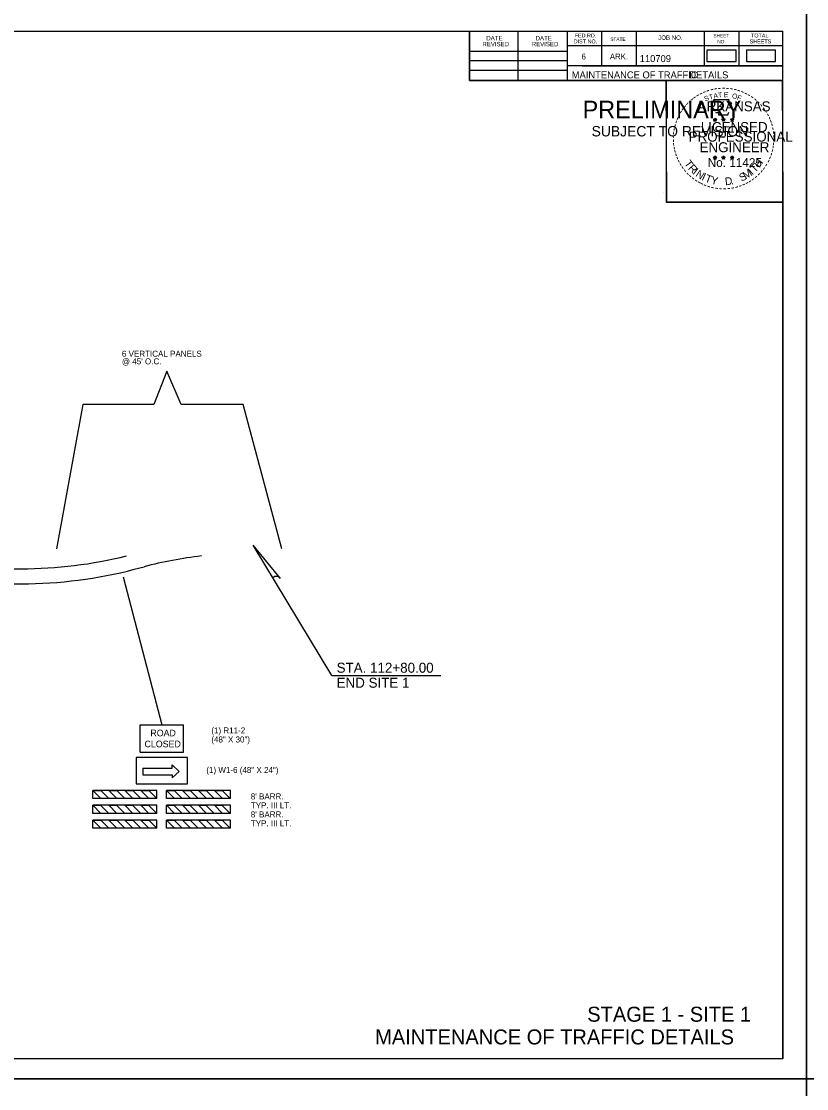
# Model space of a CAD drawing. Extents: x 2829243 to 2838161, y 467639 to 474695.
# Drawn here: x 2830368 to 2831153, y 471502 to 472569 of the extents above; entities that cross this region are included whole.
import ezdxf

# ---------------------------------------------------------------- set-up
doc = ezdxf.new("R2010")
doc.units = 0
for name, color, linetype in [('Default', 7, 'Continuous'), ('R_Border', 7, 'Continuous'), ('R_Border PE', 7, 'Continuous'), ('R_Border Prem', 7, 'Continuous'), ('R_Dimension', 7, 'Continuous'), ('R_MOT', 7, 'Continuous'), ('R_No Plot', 7, 'Continuous')]:
    doc.layers.add(name, color=color, linetype=linetype)

msp = doc.modelspace()

# ---------------------------------------------------------------- linework, layer by layer
at = {"layer": 'Default'}
for points in [[(2831053.2, 472528.5), (2831082.4, 472528.5), (2831082.4, 472540), (2831053.2, 472540)], [(2831092.6, 472528.5), (2831121.7, 472528.5), (2831121.7, 472540), (2831092.6, 472540)]]:
    msp.add_lwpolyline(points, close=True, dxfattribs=at)
at = {"layer": 'R_Border'}
for p, q in [((2829548.2, 472559), (2831129.1, 472559)), ((2830815.9, 472509.6), (2830815.9, 472559)), ((2830864.3, 472509.6), (2830864.3, 472559)), ((2830913.6, 472559), (2830913.6, 472509.6)), ((2830947.8, 472559), (2830947.8, 472524.3)), ((2830982.5, 472559), (2830982.5, 472524.3)), ((2831050.4, 472559), (2831050.4, 472524.3)), ((2831085.1, 472559), (2831085.1, 472524.3)), ((2831129.1, 471531.7), (2831129.1, 472559)), ((2831129.1, 472544.3), (2830913.6, 472544.3)), ((2831129.1, 472544.4), (2831129.1, 472544.4)), ((2830815.9, 472538.9), (2830913.6, 472538.9)), ((2830815.9, 472529.6), (2830913.6, 472529.6)), ((2831129.1, 472524.3), (2830913.6, 472524.3)), ((2830928.4, 472524.3), (2831129.1, 472524.3)), ((2830815.9, 472519.9), (2830913.6, 472519.9)), ((2831129.1, 472509.6), (2830815.9, 472509.6)), ((2831129.1, 471531.7), (2829548.2, 471531.7))]:
    msp.add_line(p, q, dxfattribs=at)
at = {"layer": 'R_Border PE'}
for p, q in [((2831059.6, 472470.8), (2831061.3, 472470.3)), ((2831059.6, 472470.8), (2831060.8, 472470.6)), ((2831059.6, 472470.8), (2831060.8, 472470.2)), ((2831060.2, 472468.8), (2831061.3, 472470.3)), ((2831060.2, 472468.8), (2831060.9, 472470)), ((2831060.2, 472468.8), (2831061.3, 472469.9)), ((2831061.3, 472472.1), (2831061.1, 472470.9)), ((2831061.3, 472470.3), (2831061.3, 472472.1)), ((2831061.3, 472472.1), (2831061.6, 472470.9)), ((2831063, 472470.8), (2831061.3, 472470.3)), ((2831062.4, 472468.8), (2831061.3, 472470.3)), ((2831062.4, 472468.8), (2831061.3, 472469.9)), ((2831063, 472470.8), (2831061.6, 472470.6)), ((2831062.4, 472468.8), (2831061.7, 472470.3)), ((2831063, 472470.8), (2831062, 472470.3)), ((2831067.9, 472470.8), (2831069.7, 472470.3)), ((2831067.9, 472470.8), (2831069.2, 472470.6)), ((2831067.9, 472470.8), (2831069.1, 472470.2)), ((2831068.6, 472468.8), (2831069.7, 472470.3)), ((2831068.6, 472468.8), (2831069.2, 472470)), ((2831068.6, 472468.8), (2831069.7, 472469.9)), ((2831069.7, 472472.1), (2831069.5, 472470.9)), ((2831069.7, 472470.3), (2831069.7, 472472.1)), ((2831069.7, 472472.1), (2831069.9, 472470.9)), ((2831071.4, 472470.8), (2831069.7, 472470.3)), ((2831070.7, 472468.8), (2831069.7, 472470.3)), ((2831070.7, 472468.8), (2831069.7, 472469.9)), ((2831071.4, 472470.8), (2831070, 472470.6)), ((2831070.7, 472468.8), (2831070, 472470.3)), ((2831071.4, 472470.8), (2831070.4, 472470.3)), ((2831076.7, 472470.8), (2831078.5, 472470.2)), ((2831076.7, 472470.8), (2831078, 472470.6)), ((2831076.7, 472470.8), (2831077.9, 472470.2)), ((2831077.4, 472468.7), (2831078.5, 472470.2)), ((2831077.4, 472468.7), (2831078, 472470)), ((2831077.4, 472468.7), (2831078.5, 472469.8)), ((2831078.5, 472472.1), (2831078.3, 472470.8)), ((2831078.5, 472470.2), (2831078.5, 472472.1)), ((2831078.5, 472472.1), (2831078.7, 472470.8)), ((2831080.2, 472470.8), (2831078.5, 472470.2)), ((2831079.5, 472468.7), (2831078.5, 472470.2)), ((2831079.5, 472468.7), (2831078.5, 472469.8)), ((2831080.2, 472470.8), (2831078.8, 472470.5)), ((2831079.5, 472468.7), (2831078.9, 472470.2)), ((2831080.2, 472470.8), (2831079.2, 472470.3)), ((2831059.5, 472433), (2831061.3, 472432.4)), ((2831059.5, 472433), (2831060.8, 472432.8)), ((2831059.5, 472433), (2831060.7, 472432.4)), ((2831060.2, 472430.9), (2831061.3, 472432.4)), ((2831060.2, 472430.9), (2831060.8, 472432.2)), ((2831060.2, 472430.9), (2831061.3, 472432)), ((2831061.3, 472434.3), (2831061.1, 472433)), ((2831061.3, 472432.4), (2831061.3, 472434.3)), ((2831061.3, 472434.3), (2831061.5, 472433)), ((2831063, 472433), (2831061.3, 472432.4)), ((2831062.4, 472430.9), (2831061.3, 472432.4)), ((2831062.4, 472430.9), (2831061.3, 472432)), ((2831063, 472433), (2831061.6, 472432.7)), ((2831062.4, 472430.9), (2831061.7, 472432.4)), ((2831063, 472433), (2831062, 472432.5)), ((2831067.9, 472433), (2831069.6, 472432.4)), ((2831067.9, 472433), (2831069.2, 472432.8)), ((2831067.9, 472433), (2831069.1, 472432.4)), ((2831068.6, 472430.9), (2831069.6, 472432.4)), ((2831068.6, 472430.9), (2831069.2, 472432.2)), ((2831068.6, 472430.9), (2831069.6, 472432)), ((2831069.6, 472434.3), (2831069.4, 472433)), ((2831069.6, 472432.4), (2831069.6, 472434.3)), ((2831069.6, 472434.3), (2831069.9, 472433)), ((2831071.4, 472433), (2831069.6, 472432.4)), ((2831070.7, 472430.9), (2831069.6, 472432.4)), ((2831070.7, 472430.9), (2831069.6, 472432)), ((2831071.4, 472433), (2831069.9, 472432.7)), ((2831070.7, 472430.9), (2831070, 472432.4)), ((2831071.4, 472433), (2831070.4, 472432.5)), ((2831076.7, 472432.9), (2831078.5, 472432.4)), ((2831076.7, 472432.9), (2831078, 472432.7)), ((2831076.7, 472432.9), (2831077.9, 472432.3)), ((2831077.4, 472430.9), (2831078.5, 472432.4)), ((2831077.4, 472430.9), (2831078, 472432.1)), ((2831077.4, 472430.9), (2831078.5, 472432)), ((2831078.5, 472434.2), (2831078.3, 472432.9)), ((2831078.5, 472432.4), (2831078.5, 472434.2)), ((2831078.5, 472434.2), (2831078.7, 472433)), ((2831080.2, 472432.9), (2831078.5, 472432.4)), ((2831079.5, 472430.9), (2831078.5, 472432.4)), ((2831079.5, 472430.9), (2831078.5, 472432)), ((2831080.2, 472432.9), (2831078.8, 472432.7)), ((2831079.5, 472430.9), (2831078.9, 472432.3)), ((2831080.2, 472432.9), (2831079.2, 472432.4))]:
    msp.add_line(p, q, dxfattribs=at)
for points in [[(2831059.8, 472490.2), (2831061.1, 472486.1)], [(2831077.3, 472485.6), (2831078, 472487), (2831074.6, 472486.9), (2831075.4, 472490.2), (2831059.8, 472490.2)], [(2831061.3, 472472.1), (2831062.4, 472468.8), (2831059.6, 472470.8), (2831063, 472470.8), (2831060.2, 472468.8), (2831061.3, 472472.1)], [(2831062.2, 472478.1), (2831062.2, 472477.7), (2831065, 472477.6), (2831064.8, 472475.2), (2831074.1, 472475.2), (2831075.1, 472477.9)], [(2831069.7, 472472.1), (2831070.7, 472468.8), (2831067.9, 472470.8), (2831071.4, 472470.8), (2831068.6, 472468.8), (2831069.7, 472472.1)], [(2831078.5, 472472.1), (2831079.5, 472468.7), (2831076.7, 472470.8), (2831080.2, 472470.8), (2831077.4, 472468.7), (2831078.5, 472472.1)], [(2831061.3, 472434.3), (2831062.4, 472430.9), (2831059.5, 472433), (2831063, 472433), (2831060.2, 472430.9), (2831061.3, 472434.3)], [(2831069.6, 472434.3), (2831070.7, 472430.9), (2831067.9, 472433), (2831071.4, 472433), (2831068.6, 472430.9), (2831069.6, 472434.3)], [(2831078.5, 472434.2), (2831079.5, 472430.9), (2831076.7, 472432.9), (2831080.2, 472432.9), (2831077.4, 472430.9), (2831078.5, 472434.2)]]:
    msp.add_lwpolyline(points, dxfattribs=at)
for centre, radius in [((2831061.3, 472470.3), 0.861), ((2831061.3, 472470.3), 0.723), ((2831061.3, 472470.3), 0.579), ((2831061.3, 472470.3), 0.495), ((2831061.3, 472470.3), 0.374), ((2831061.3, 472470.3), 0.248), ((2831061.3, 472470.3), 0.148), ((2831069.7, 472470.3), 0.861), ((2831069.7, 472470.3), 0.723), ((2831069.7, 472470.3), 0.579), ((2831069.7, 472470.3), 0.495), ((2831069.7, 472470.3), 0.374), ((2831069.7, 472470.3), 0.248), ((2831069.7, 472470.3), 0.148), ((2831078.5, 472470.2), 0.861), ((2831078.5, 472470.2), 0.723), ((2831078.5, 472470.2), 0.579), ((2831078.5, 472470.2), 0.495), ((2831078.5, 472470.2), 0.374), ((2831078.5, 472470.2), 0.248), ((2831078.5, 472470.2), 0.148), ((2831061.3, 472432.4), 0.861), ((2831061.3, 472432.4), 0.723), ((2831061.3, 472432.4), 0.579), ((2831061.3, 472432.4), 0.495), ((2831061.3, 472432.4), 0.374), ((2831061.3, 472432.4), 0.248), ((2831061.3, 472432.4), 0.148), ((2831069.6, 472432.4), 0.861), ((2831069.6, 472432.4), 0.723), ((2831069.6, 472432.4), 0.579), ((2831069.6, 472432.4), 0.495), ((2831069.6, 472432.4), 0.374), ((2831069.6, 472432.4), 0.248), ((2831069.6, 472432.4), 0.148), ((2831078.5, 472432.4), 0.861), ((2831078.5, 472432.4), 0.723), ((2831078.5, 472432.4), 0.579), ((2831078.5, 472432.4), 0.495), ((2831078.5, 472432.4), 0.374), ((2831078.5, 472432.4), 0.248), ((2831078.5, 472432.4), 0.148)]:
    msp.add_circle(centre, radius, dxfattribs=at)
at = {"layer": 'R_Dimension'}
for p, q in [((2830626.8, 472012), (2830599.6, 472045.1)), ((2830678, 471914.9), (2830599.6, 472045.1)), ((2830678, 471914.9), (2830787, 471914.9))]:
    msp.add_line(p, q, dxfattribs=at)
msp.add_arc((2830622.7, 472008.8), 5.2, 37.7002, 131.115, dxfattribs=at)
at = {"layer": 'R_MOT'}
for p, q in [((2830469.6, 472013.5), (2830508.2, 471865.5)), ((2830486.4, 471838.3), (2830486.4, 471865.5)), ((2830486.4, 471865.5), (2830529.9, 471865.5)), ((2830529.9, 471838.3), (2830529.9, 471865.5)), ((2830486.4, 471838.3), (2830529.9, 471838.3)), ((2830489, 471822.3), (2830518.4, 471822.3)), ((2830489, 471822.3), (2830489, 471815.8)), ((2830518.4, 471822.3), (2830518.4, 471825.6)), ((2830518.4, 471825.6), (2830525.5, 471819)), ((2830525.5, 471819), (2830518.4, 471812.5)), ((2830489, 471815.8), (2830518.4, 471815.8)), ((2830518.4, 471815.8), (2830518.4, 471812.5)), ((2830503.2, 471800.1), (2830439.2, 471800.1)), ((2830439.2, 471792), (2830439.2, 471800.1)), ((2830503.2, 471792), (2830503.2, 471800.1)), ((2830576.7, 471800.1), (2830512.7, 471800.1)), ((2830512.7, 471792), (2830512.7, 471800.1)), ((2830576.7, 471792), (2830576.7, 471800.1)), ((2830439.2, 471792.1), (2830439.2, 471792.1)), ((2830503.2, 471792), (2830439.2, 471792)), ((2830512.7, 471792.1), (2830512.7, 471792.1)), ((2830576.7, 471792), (2830512.7, 471792)), ((2830503.2, 471785.2), (2830439.2, 471785.2)), ((2830439.2, 471777.1), (2830439.2, 471785.2)), ((2830439.2, 471777.1), (2830439.2, 471785.2)), ((2830503.2, 471777.1), (2830439.2, 471777.1)), ((2830503.2, 471777.1), (2830503.2, 471785.2)), ((2830576.7, 471785.2), (2830512.7, 471785.2)), ((2830512.7, 471777.1), (2830512.7, 471785.2)), ((2830512.7, 471777.1), (2830512.7, 471785.2)), ((2830576.7, 471777.1), (2830512.7, 471777.1)), ((2830576.7, 471777.1), (2830576.7, 471785.2)), ((2830503.2, 471770.3), (2830439.2, 471770.3)), ((2830439.2, 471762.3), (2830439.2, 471770.3)), ((2830503.2, 471762.3), (2830503.2, 471770.3)), ((2830576.7, 471770.3), (2830512.7, 471770.3)), ((2830512.7, 471762.3), (2830512.7, 471770.3)), ((2830576.7, 471762.3), (2830576.7, 471770.3)), ((2830503.2, 471762.3), (2830439.2, 471762.3)), ((2830576.7, 471762.3), (2830512.7, 471762.3))]:
    msp.add_line(p, q, dxfattribs=at)
msp.add_lwpolyline([(2830628, 472041.6), (2830589.3, 472185.9), (2830527.4, 472185.9), (2830513.2, 472219.1), (2830500.1, 472185.9), (2830429.1, 472185.9), (2830402.9, 472041.5)], dxfattribs=at)
for points in [[(2830533.9, 471833.1), (2830482.4, 471833.1), (2830482.4, 471806.7), (2830533.9, 471806.7)], [(2830439.2, 471800.1), (2830447, 471800), (2830455, 471792.1), (2830447.2, 471792.1)], [(2830455.2, 471800.1), (2830463, 471800), (2830471, 471792.1), (2830463.2, 471792.1)], [(2830471.2, 471800.1), (2830479, 471800), (2830487, 471792.1), (2830479.2, 471792.1)], [(2830487.2, 471800.1), (2830495, 471800), (2830503, 471792.1), (2830495.2, 471792.1)], [(2830512.7, 471800.1), (2830520.6, 471800), (2830528.6, 471792.1), (2830520.7, 471792.1)], [(2830528.7, 471800.1), (2830536.6, 471800), (2830544.6, 471792.1), (2830536.7, 471792.1)], [(2830544.7, 471800.1), (2830552.6, 471800), (2830560.6, 471792.1), (2830552.7, 471792.1)], [(2830560.7, 471800.1), (2830568.6, 471800), (2830576.6, 471792.1), (2830568.7, 471792.1)], [(2830439.2, 471785.2), (2830447, 471785.1), (2830455, 471777.1), (2830447.2, 471777.1)], [(2830455.2, 471785.2), (2830463, 471785.1), (2830471, 471777.1), (2830463.2, 471777.1)], [(2830471.2, 471785.2), (2830479, 471785.1), (2830487, 471777.1), (2830479.2, 471777.1)], [(2830487.2, 471785.2), (2830495, 471785.1), (2830503, 471777.1), (2830495.2, 471777.1)], [(2830512.7, 471785.2), (2830520.6, 471785.1), (2830528.6, 471777.1), (2830520.7, 471777.1)], [(2830528.7, 471785.2), (2830536.6, 471785.1), (2830544.6, 471777.1), (2830536.7, 471777.1)], [(2830544.7, 471785.2), (2830552.6, 471785.1), (2830560.6, 471777.1), (2830552.7, 471777.1)], [(2830560.7, 471785.2), (2830568.6, 471785.1), (2830576.6, 471777.1), (2830568.7, 471777.1)], [(2830439.2, 471770.3), (2830447, 471770.3), (2830455, 471762.3), (2830447.2, 471762.3)], [(2830455.2, 471770.3), (2830463, 471770.3), (2830471, 471762.3), (2830463.2, 471762.3)], [(2830471.2, 471770.3), (2830479, 471770.3), (2830487, 471762.3), (2830479.2, 471762.3)], [(2830487.2, 471770.3), (2830495, 471770.3), (2830503, 471762.3), (2830495.2, 471762.3)], [(2830512.7, 471770.3), (2830520.6, 471770.3), (2830528.6, 471762.3), (2830520.7, 471762.3)], [(2830528.7, 471770.3), (2830536.6, 471770.3), (2830544.6, 471762.3), (2830536.7, 471762.3)], [(2830544.7, 471770.3), (2830552.6, 471770.3), (2830560.6, 471762.3), (2830552.7, 471762.3)], [(2830560.7, 471770.3), (2830568.6, 471770.3), (2830576.6, 471762.3), (2830568.7, 471762.3)]]:
    msp.add_lwpolyline(points, close=True, dxfattribs=at)
at = {"layer": 'R_No Plot'}
for p, q in [((2831009.3, 472397.3), (2831009.3, 472397.3)), ((2830291.5, 472021.6), (2830367.6, 472021.6)), ((2830480.6, 472021.1), (2830490.3, 472023.6)), ((2830291.5, 472006.6), (2830367.6, 472006.6)), ((2829486.2, 471511.8), (2831152.9, 471511.8)), ((2829486.2, 471511.8), (2831152.9, 471511.8))]:
    msp.add_line(p, q, dxfattribs=at)
for points in [[(2829486.2, 472578.4), (2831152.9, 472578.4), (2831152.9, 471511.8), (2829486.2, 471511.8)], [(2831152.9, 472578.4), (2832819.6, 472578.4), (2832819.6, 471511.8), (2831152.9, 471511.8)], [(2830717.8, 472559), (2830815.9, 472559), (2830815.9, 472509.6), (2830896.5, 472509.6), (2831012.5, 472509.6), (2831012.5, 472387.9), (2831129.1, 472387.9), (2831129.1, 471531.7), (2829548.2, 471531.7), (2829548.2, 472559)], [(2831012.5, 472509.6), (2831128.5, 472509.6), (2831129.1, 472387.9), (2831013.1, 472387.9)], [(2829486.2, 471511.8), (2831152.9, 471511.8), (2831152.9, 470445.1), (2829486.2, 470445.1)], [(2831152.9, 471511.8), (2832819.6, 471511.8), (2832819.6, 470445.1), (2831152.9, 470445.1)]]:
    msp.add_lwpolyline(points, close=True, dxfattribs=at)
for centre, radius, start, end in [((2830367.6, 472454.8), 433.2, 270, 284.0555), ((2830599.6, 471604.4), 433.2, 96.8786, 104.6039), ((2830367.6, 472454.8), 448.2, 270, 284.6039)]:
    msp.add_arc(centre, radius, start, end, dxfattribs=at)

# ---------------------------------------------------------------- texts
at = {"layer": 'R_Border'}
for s, height, p in [('DATE', 4.4, (2830832.6, 472549.7)), ('DATE', 4.4, (2830881.9, 472549.7)), ('FED.RD.', 3.91, (2830921, 472552.6)), ('JOB NO.', 4.4, (2831004.5, 472550.2)), ('SHEET', 3.42, (2831059.7, 472552.6)), ('TOTAL', 3.91, (2831097.3, 472552.6)), ('REVISED', 4.4, (2830828.7, 472543.8)), ('REVISED', 4.4, (2830878, 472543.8)), ('DIST.NO.', 3.91, (2830920, 472546.7)), ('STATE', 3.42, (2830956.6, 472549.2)), ('NO.', 3.42, (2831063.6, 472546.7)), ('SHEETS', 3.91, (2831095.9, 472546.7)), ('6', 5.86, (2830927.8, 472530.6)), ('ARK.', 5.86, (2830956.1, 472530.6)), ('110709', 7, (2830986, 472528)), ('MAINTENANCE OF TRAFFIC', 7, (2830918, 472511.7)), (' DETAILS', 7, (2831033, 472511.7)), ('STAGE 1 - SITE 1 ', 15, (2830933.5, 471568.9)), ('MAINTENANCE OF TRAFFIC DETAILS', 15, (2830721.4, 471546.2))]:
    msp.add_text(s, height=height, dxfattribs=at).set_placement(p)
at = {"layer": 'R_Border PE'}
for s, height, rotation, p in [('-', 8, 19.1761, (2831053.5, 472495.9)), ('-', 8, 13.6302, (2831057.3, 472497.1)), ('-', 8, 10.2193, (2831060.7, 472497.9)), ('-', 8, 5.8968, (2831064.3, 472498.4)), ('-', 8, 0.1862, (2831068.2, 472498.8)), ('-', 8, 357.743, (2831071.8, 472498.7)), ('-', 8, 352.1617, (2831075.5, 472498.5)), ('-', 8, 347.2049, (2831079.1, 472497.9)), ('-', 8, 342.3362, (2831082.3, 472497.1)), ('-', 8, 42.9622, (2831036.8, 472485.1)), ('-', 8, 38.9507, (2831038.9, 472487.2)), ('-', 8, 36.2317, (2831041.3, 472489.1)), ('-', 8, 34.0636, (2831044.2, 472491.1)), ('-', 8, 28.7918, (2831047.2, 472492.9)), ('-', 8, 24.3072, (2831050.3, 472494.5)), ('S', 5, 21.594, (2831051.5, 472488.6)), ('T', 5, 16.4036, (2831056.1, 472490.3)), ('A', 5, 11.2132, (2831060.2, 472491.5)), ('T', 5, 6.0228, (2831064.5, 472492.4)), ('E', 5, 0.8323, (2831070, 472492.9)), ('O', 5, 350.4515, (2831078, 472491.9)), ('F', 5, 340.0707, (2831082.8, 472490.7)), ('-', 8, 337.8551, (2831085.9, 472496)), ('-', 8, 334.1211, (2831089.1, 472494.6)), ('-', 8, 329.6409, (2831092, 472493.2)), ('-', 8, 325.8627, (2831095.2, 472491.4)), ('-', 8, 320.5297, (2831098.3, 472489.3)), ('-', 8, 58.0706, (2831028.8, 472474.9)), ('-', 8, 54.2325, (2831030.4, 472477.5)), ('-', 8, 50.6142, (2831032.5, 472480.3)), ('-', 8, 48.4231, (2831034.5, 472482.8)), ('-', 8, 315.5786, (2831101.2, 472486.8)), ('-', 8, 309.8797, (2831104.1, 472484.1)), ('-', 8, 306.6522, (2831106.7, 472481.1)), ('-', 7, 303.6753, (2831109.1, 472478.2)), ('-', 8, 72.3945, (2831024.9, 472465.6)), ('-', 8, 67.7743, (2831026, 472468.7)), ('-', 8, 62.8713, (2831027.2, 472471.8)), ('-', 8, 299.6684, (2831110.7, 472475.2)), ('-', 8, 294.6628, (2831112.4, 472472.2)), ('-', 8, 290.5728, (2831113.6, 472469.3)), ('-', 8, 85.1863, (2831022.8, 472455)), ('-', 8, 81.2013, (2831023.2, 472458.4)), ('-', 8, 75.461, (2831023.9, 472462)), ('-', 8, 285.1233, (2831114.8, 472466.4)), ('-', 8, 280.5493, (2831115.8, 472462.7)), ('-', 8, 276.5962, (2831116.6, 472458.8)), ('-', 8, 94.1959, (2831022.9, 472447.9)), ('-', 8, 89.0622, (2831022.7, 472451.5)), ('-', 8, 98.9479, (2831023.2, 472444.5)), ('-', 8, 263.5172, (2831117, 472448.7)), ('-', 8, 274.3301, (2831116.9, 472455.2)), ('-', 8, 269.9407, (2831117.1, 472452)), ('-', 8, 101.7149, (2831023.9, 472440.9)), ('-', 8, 105.4578, (2831024.7, 472437.9)), ('-', 8, 109.0874, (2831025.8, 472434.7)), ('-', 8, 252.8681, (2831115.2, 472438.5)), ('-', 8, 255.7626, (2831116.1, 472442.1)), ('-', 8, 260.9953, (2831116.6, 472445.4)), ('-', 8, 114.0643, (2831027.1, 472431.7)), ('-', 8, 115.7289, (2831028.6, 472428.7)), ('-', 8, 120.4471, (2831030.4, 472425.7)), ('T', 7.7, 306.0406, (2831030.1, 472426.6)), ('R', 7.7, 314.005, (2831033.9, 472421.4)), ('T', 7.7, 46.6444, (2831101.2, 472417.1)), ('H', 7.7, 54.6088, (2831105.7, 472421.8)), ('-', 8, 239.0712, (2831110.8, 472428.2)), ('-', 8, 244.6197, (2831112.8, 472431.9)), ('-', 8, 247.8887, (2831114.1, 472435.1)), ('-', 8, 125.8934, (2831032.4, 472422.9)), ('-', 8, 130.7181, (2831034.7, 472420.2)), ('-', 8, 134.2238, (2831037.3, 472417.4)), ('-', 8, 138.9338, (2831039.9, 472415.1)), ('I', 7.7, 321.9694, (2831038.4, 472416.7)), ('N', 7.7, 326.5002, (2831041.2, 472414.4)), ('I', 7.7, 335.3603, (2831047.3, 472410.4)), ('T', 7.7, 339.8912, (2831050.6, 472408.8)), ('S', 7.7, 26.9312, (2831087.8, 472408.4)), ('M', 7.7, 32.6563, (2831092, 472410.5)), ('I', 7.7, 42.1136, (2831098.4, 472414.7)), ('-', 8, 225.7653, (2831104.2, 472419.3)), ('-', 8, 231.2538, (2831106.6, 472422.1)), ('-', 8, 233.8452, (2831108.8, 472424.9)), ('-', 8, 144.6463, (2831042.7, 472413.1)), ('-', 8, 148.0898, (2831045.5, 472411.2)), ('-', 8, 151.5704, (2831048.4, 472409.6)), ('-', 8, 154.6002, (2831051, 472408.4)), ('-', 8, 158.5612, (2831054.1, 472407.1)), ('-', 8, 162.7983, (2831057.6, 472406)), ('Y', 7.7, 347.8556, (2831056.7, 472406.6)), ('D', 7.7, 6.3969, (2831071.6, 472404.8)), ('.', 7.7, 13.7642, (2831077.6, 472405.4)), ('-', 8, 200.7184, (2831087.2, 472407.7)), ('-', 8, 204.2516, (2831090.3, 472409.1)), ('-', 8, 207.3568, (2831093.4, 472410.7)), ('-', 8, 212.2491, (2831096.2, 472412.4)), ('-', 8, 215.7363, (2831098.9, 472414.4)), ('-', 8, 221.0851, (2831101.6, 472416.7)), ('-', 8, 167.5555, (2831061.1, 472405.2)), ('-', 8, 173.1155, (2831065, 472404.7)), ('-', 8, 176.5183, (2831068.7, 472404.4)), ('-', 8, 181.5918, (2831072.5, 472404.5)), ('-', 8, 185.8167, (2831076.5, 472404.9)), ('-', 8, 191.2858, (2831080.2, 472405.5)), ('-', 8, 195.4743, (2831083.8, 472406.5))]:
    msp.add_text(s, height=height, rotation=rotation, dxfattribs=at).set_placement(p)
for s, height, p in [('ARKANSAS', 10, (2831044, 472478.8)), ('LICENSED', 10, (2831047, 472458.1)), ('DWB', 0.05, (2831061.2, 472470.3)), ('DWB', 0.05, (2831069.6, 472470.3)), ('DWB', 0.05, (2831078.4, 472470.2)), ('PROFESSIONAL', 10, (2831034.9, 472448.5)), ('ENGINEER', 10, (2831045.8, 472437.9)), ('No. 11425', 8.78, (2831054, 472423.2)), ('DWB', 0.05, (2831061.2, 472432.4)), ('DWB', 0.05, (2831069.6, 472432.4)), ('DWB', 0.05, (2831078.4, 472432.4))]:
    msp.add_text(s, height=height, dxfattribs=at).set_placement(p)
at = {"layer": 'R_Border Prem'}
for s, height, p in [('PRELIMINARY', 17.5, (2830928.9, 472471.9)), ('DWB', 0.05, (2830932.6, 472481.1)), ('SUBJECT TO REVISION', 10.376, (2830937.9, 472453.7))]:
    msp.add_text(s, height=height, dxfattribs=at).set_placement(p)
at = {"layer": 'R_Dimension'}
for s, p in [('STA. 112+80.00', (2830682.9, 471917.7)), ('END SITE 1', (2830682.9, 471902.7))]:
    msp.add_text(s, height=10, rotation=0.0006, dxfattribs=at).set_placement(p)
at = {"layer": 'R_MOT'}
for s, p in [('6 VERTICAL PANELS', (2830468.2, 472233.5)), ("@ 45' O.C.", (2830468.2, 472225.9))]:
    msp.add_text(s, height=6, rotation=0.0055, dxfattribs=at).set_placement(p)
for s, height, p in [('ROAD', 6.58, (2830496.7, 471854.2)), ('(1) R11-2', 6, (2830557.6, 471857)), ('CLOSED', 6.61, (2830490.8, 471843.2)), ('(48" X 30")', 6, (2830557.6, 471848)), ('(1) W1-6 (48" X 24")', 6, (2830552.6, 471817.5)), ("8' BARR.", 6, (2830597.1, 471791.1)), ('TYP. III LT.', 6, (2830597.1, 471782.1)), ("8' BARR.", 6, (2830597.1, 471773.1)), ('TYP. III LT.', 6, (2830597.1, 471764.1))]:
    msp.add_text(s, height=height, dxfattribs=at).set_placement(p)

doc.saveas('drawing.dxf')
